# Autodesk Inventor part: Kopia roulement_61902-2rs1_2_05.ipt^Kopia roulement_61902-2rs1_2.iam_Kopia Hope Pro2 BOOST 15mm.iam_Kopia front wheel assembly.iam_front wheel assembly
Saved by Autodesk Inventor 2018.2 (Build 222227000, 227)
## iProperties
Created: 2017-09
Part Number: Kopia roulement_61902-2rs1_2_05.ipt^Kopia roulement_61902-2rs1_2.iam_Kopia Hope Pro2 BOOST 15mm.iam_Kopia front wheel assembly.iam_front wheel assembly
Material: Ogólny
Document SubType Name: Modeling
Designer: Tomasz
Density: 1 g/cm^3
Appearance: Domyślna
Author: Tomasz
Sending System: SolidWorks 2017
Last Author: Tomasz
Last Saved: 2017-09-11
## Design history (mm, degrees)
